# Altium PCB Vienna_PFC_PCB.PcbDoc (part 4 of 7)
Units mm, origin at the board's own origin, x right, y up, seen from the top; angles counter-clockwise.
Board outline 447.04 x 302.51 mm, 6 copper layers (Top Layer, Signal Layer 1, Signal Layer 2, Signal Layer 3, Signal Layer 4, Bottom Layer), stack 1.231 mm thick; 630 components, 255 nets, 1656 pads, 941 vias.
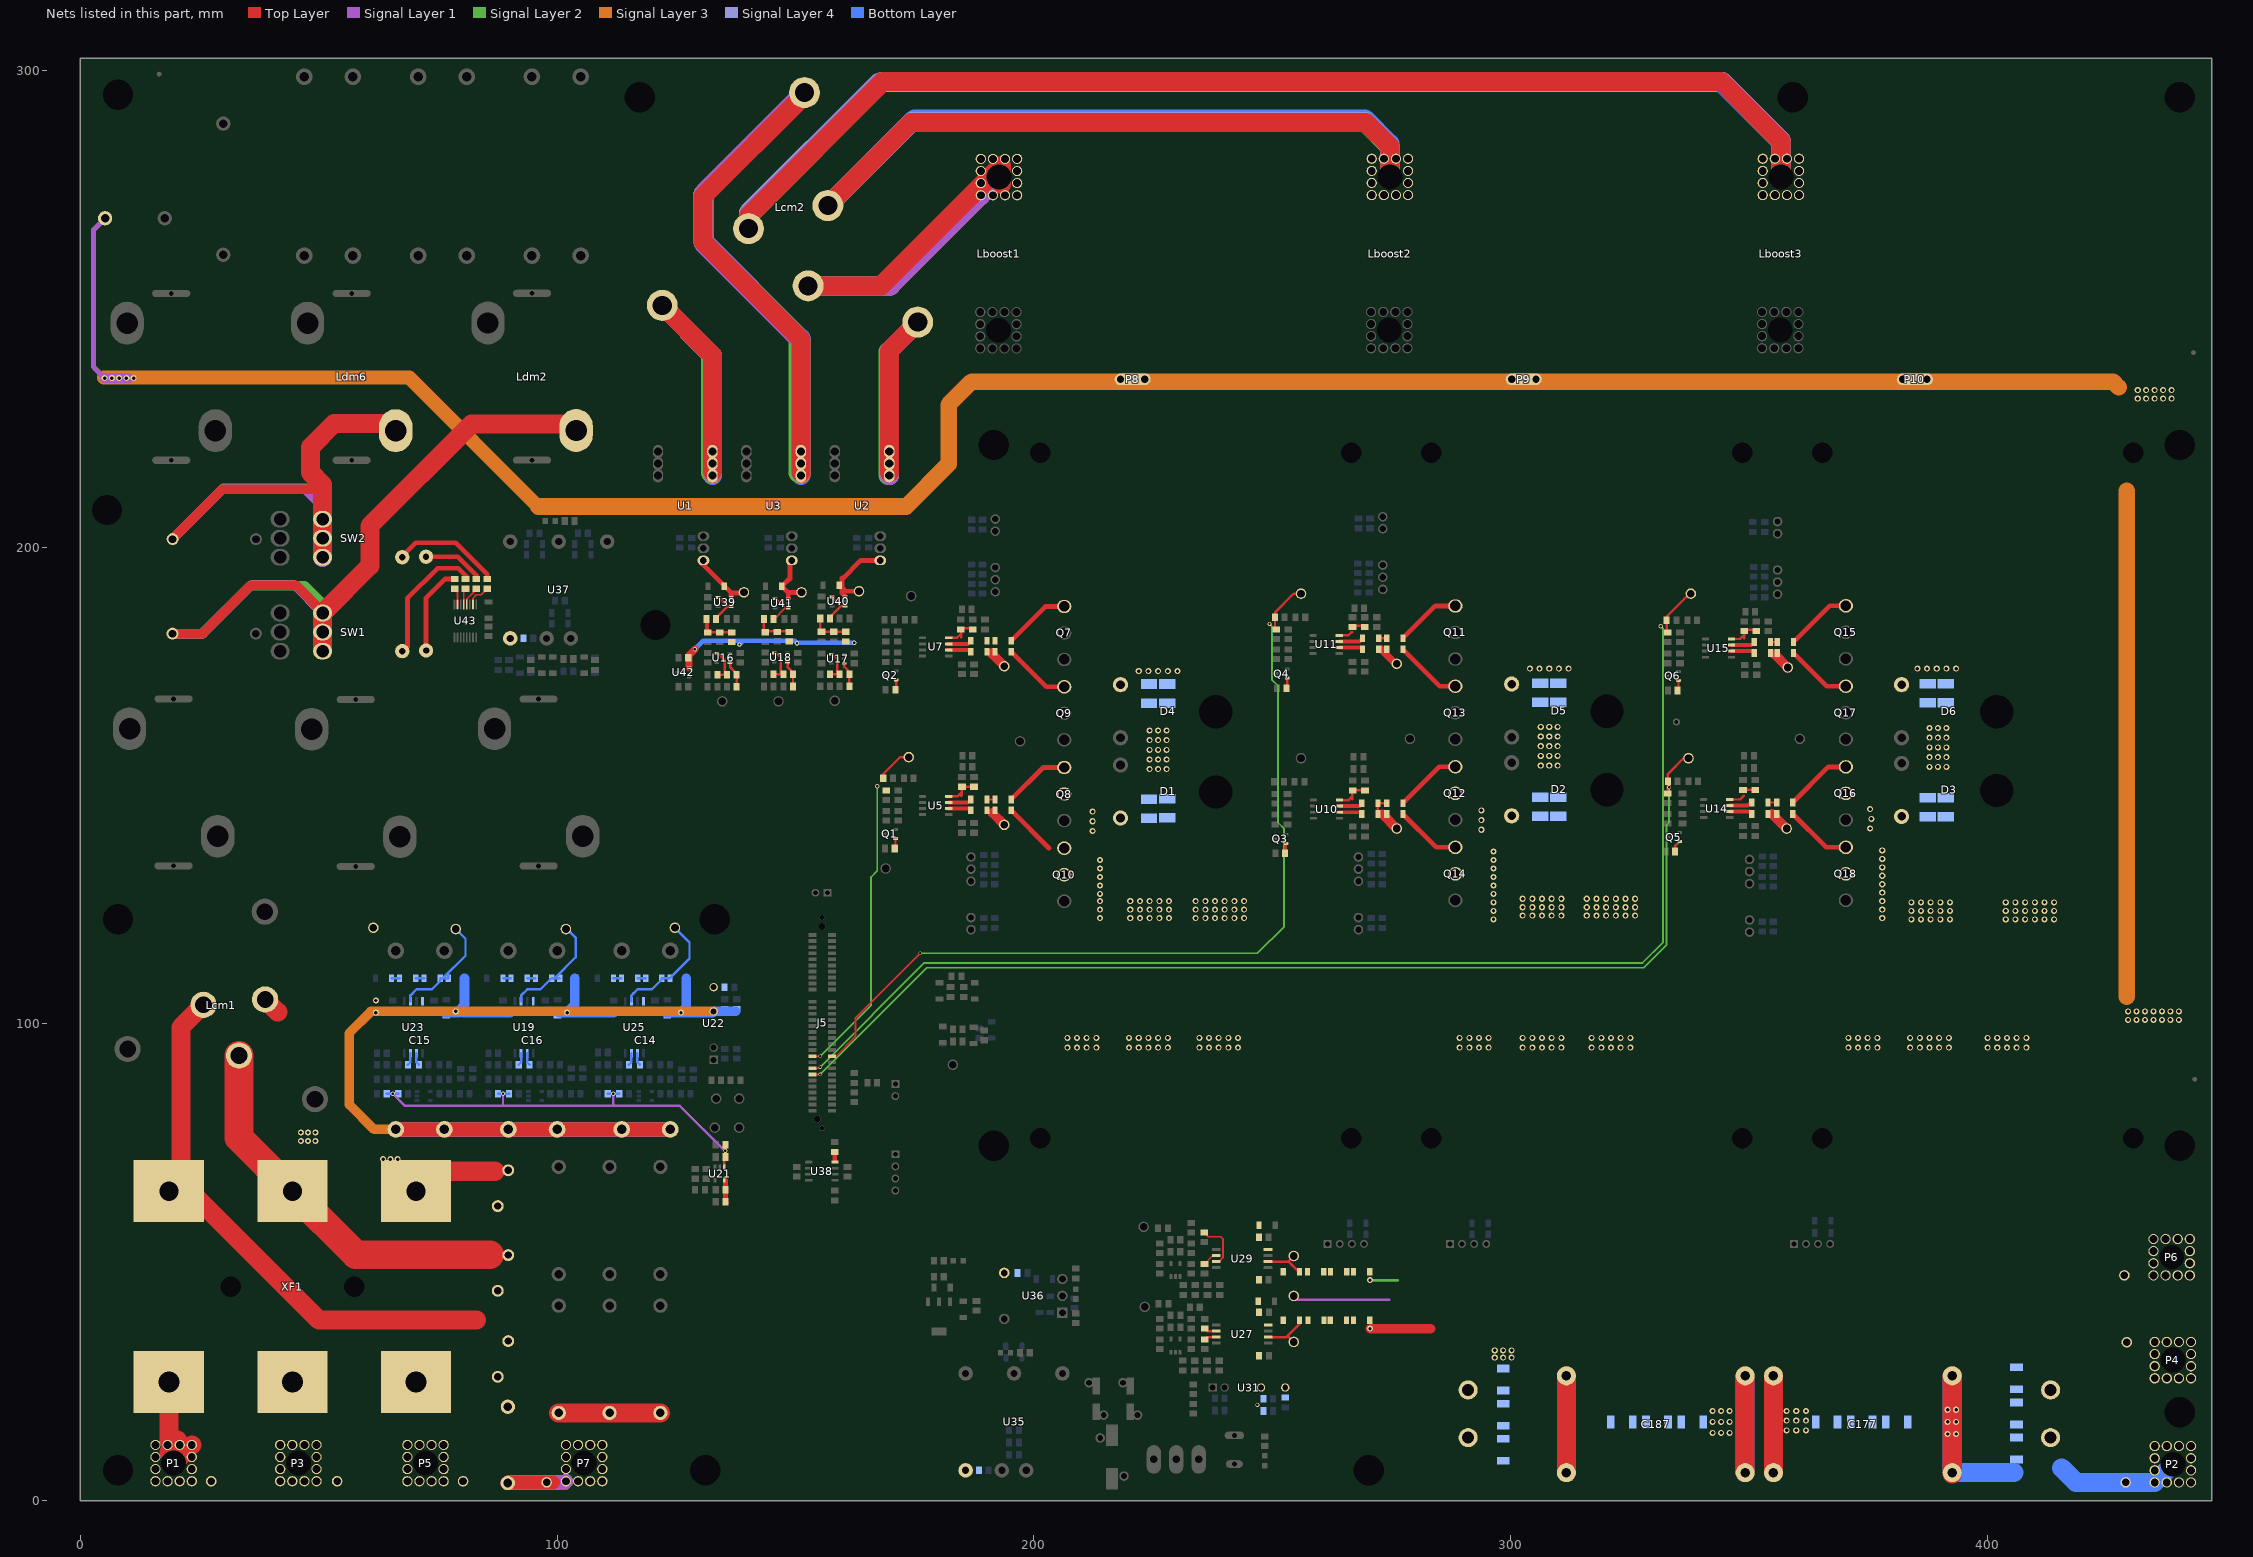
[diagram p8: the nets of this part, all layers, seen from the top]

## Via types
v1: diameter 1.27, hole 0.711, Top Layer to Bottom Layer, 487 vias
v2: diameter 0.889, hole 0.508, Top Layer to Bottom Layer, 425 vias
v3: diameter 0.762, hole 0.457, Top Layer to Bottom Layer, 28 vias
v4: diameter 0.889/0.889/0.889/0.889/0.889/0.889 (per signal layer), hole 0.508, Top Layer to Bottom Layer, 1 vias

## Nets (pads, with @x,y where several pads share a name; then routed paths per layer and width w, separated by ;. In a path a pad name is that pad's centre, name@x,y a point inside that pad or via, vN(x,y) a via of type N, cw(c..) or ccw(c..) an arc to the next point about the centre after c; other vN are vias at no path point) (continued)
NetJ5_41: J5.41 R7.1 R14.2 TP_G2.1 | length 70.9
  Top Layer w0.381: J5.41@153.565,93.218 v3(155.194,93.218)
  Top Layer w0.508: R14.2@168.402,151.511 168.402,152.4 171.958,155.956 TP_G2.1@173.736,155.956
  Signal Layer 2 w0.381: v3(155.194,93.218) 165.862,103.886 165.862,111.76 165.862,130.81 167.132,132.08 v2(167.132,149.86)
NetJ5_42: J5.42 R26.1 R33.2 TP_G3.1 | length 183.9
  Top Layer w0.381: J5.42@157.625,93.218 158.496,93.218 162.56,97.282 162.56,101.219 v3(176.149,114.808)
  Top Layer w0.508: R26.1@250.825,182.753 250.571,183.007 R33.2@250.571,185.293 250.571,186.309 254.508,190.246 TP_G3.1@256.032,190.246
  Signal Layer 2 w0.381: v3(176.149,114.808) 246.888,114.808 252.476,120.396 252.476,140.97 251.206,142.24 251.206,170.942 249.936,172.212 249.936,183.388 v2(249.428,183.896)
NetJ5_45: J5.45 R42.1 R49.2 TP_G5.1 | length 266.7
  Top Layer w0.381: J5.45@153.162,90.678 J5.45@153.565,90.678 154.94,90.678 v3(155.194,90.932)
  Top Layer w0.508: R42.1@332.994,182.118 332.74,182.372 R49.2@332.74,184.658 332.74,185.42 337.566,190.246 TP_G5.1@337.82,190.246
  Signal Layer 2 w0.381: v3(155.194,90.932) 177.038,112.776 327.66,112.776 331.978,117.094 331.978,182.88 v2(331.47,183.388)
NetJ5_47: J5.47 R40.1 R47.2 TP_G6.1 | length 233.4
  Top Layer w0.381: J5.47@153.565,89.408 v3(155.194,89.408)
  Top Layer w0.508: R40.1@332.994,148.336 332.994,152.4 336.296,155.702 TP_G6.1@337.312,155.702
  Signal Layer 2 w0.381: v3(155.194,89.408) 177.546,111.76 327.914,111.76 332.677,116.523 332.677,141.669 333.248,142.24 v2(333.248,149.606)
NetL5_1: L5.1 U22.7
NetL7_1: L7.1 U31.7
NetLboost1_1: Lboost1.1 Lcm2.2 | length 302.3
  Top Layer w4: Lcm2.2@152.658,254.814 167.945,254.813 193.192,280.06 Lboost1.1@193.192,276.098
  Signal Layer 1 w4: Lcm2.2@152.658,254.814 169.876,254.813 Lboost1.1@188.874,273.812 Lboost1.1@192.684,277.622
  Signal Layer 2 w4: Lcm2.2@152.658,254.814 169.469,254.813 192.278,277.622 Lboost1.1@192.684,277.622
  Signal Layer 3 w4: Lcm2.2@152.658,254.814 169.876,254.813 Lboost1.1@188.874,273.812 Lboost1.1@192.684,277.622
  Signal Layer 4 w4: Lcm2.2@152.658,254.814 169.876,254.813 Lboost1.1@188.874,273.812 Lboost1.1@192.684,277.622
  Bottom Layer w4: Lcm2.2@152.658,254.814 169.876,254.813 Lboost1.1@188.874,273.812 Lboost1.1@192.684,277.622
NetLboost2_1: Lboost2.1 Lcm2.4 | length 802.7
  Top Layer w4: Lcm2.4@156.775,271.638 174.189,289.052 269.672,289.052 274.676,284.048 Lboost2.1@274.676,277.647
  Signal Layer 1 w4: Lcm2.4@156.775,271.638 174.189,289.052 269.748,289.052 274.676,284.124 Lboost2.1@274.676,277.647
  Signal Layer 2 w4: Lcm2.4@156.775,271.638 174.189,289.052 269.494,289.052 274.676,283.87 Lboost2.1@274.676,277.647
  Signal Layer 3 w4: Lcm2.4@156.775,271.638 174.189,289.052 269.748,289.052 274.676,284.124 Lboost2.1@274.676,277.647
  Signal Layer 4 w4: Lcm2.4@156.775,271.638 156.83,271.638 174.498,289.306 269.494,289.306 274.676,284.124 Lboost2.1@274.676,277.647
  Bottom Layer w4: Lcm2.4@156.775,271.638 174.951,289.814 269.494,289.814 274.676,284.632 Lboost2.1@274.676,277.647
NetLboost3_1: Lboost3.1 Lcm2.6 | length 1462.5
  Top Layer w4: Lcm2.6@140.147,266.791 140.147,269.433 168.402,297.688 344.094,297.688 356.692,285.09 Lboost3.1@356.692,277.647
  Signal Layer 1 w4: Lcm2.6@140.147,266.791 140.147,269.687 168.148,297.688 344.424,297.688 356.692,285.42 Lboost3.1@356.692,277.647
  Signal Layer 2 w4: Lcm2.6@140.147,266.791 140.147,269.433 168.402,297.688 344.424,297.688 356.692,285.42 Lboost3.1@356.692,277.647
  Signal Layer 3 w4: Lcm2.6@140.147,266.791 140.147,269.687 168.148,297.688 344.17,297.688 356.692,285.166 Lboost3.1@356.692,277.647
  Signal Layer 4 w4: Lcm2.6@140.147,266.791 140.147,270.195 167.386,297.434 344.678,297.434 356.692,285.42 Lboost3.1@356.692,277.647
  Bottom Layer w4: Lcm2.6@140.147,266.791 140.147,269.941 167.64,297.434 344.17,297.434 356.692,284.912 Lboost3.1@356.692,277.647
NetLcm1_1: Lcm1.1 TVS3.2 XF1.2 | length 117.8
  Top Layer w4: Lcm1.1@25.808,103.994 21.082,99.268 21.082,67.432 XF1.2@18.542,64.892 22.992,64.892 50.038,37.846 83.058,37.846
NetLcm1_3: Lcm1.3 TVS1.2 XF1.6 | length 24.5
  Top Layer w4: Lcm1.3@38.749,105.126 41.402,102.473 ; XF1.6@67.95,64.892 XF1.6@70.358,64.892 70.988,64.892 75.184,69.088 86.978,69.088
  other v1: 63.5,71.628 65.024,71.628 66.548,71.628 46.228,75.438 47.752,75.438 49.276,75.438 46.228,77.216 47.752,77.216 49.276,77.216
NetLcm1_5: Lcm1.5 TVS2.2 XF1.4 | length 80
  Top Layer w6: Lcm1.5@33.259,93.353 33.259,76.083 XF1.4@44.45,64.892 57.8,51.542 85.852,51.542
NetLcm2_1: Lcm2.1 U1.4 U1.5 U1.6 | length 237.7
  Top Layer w4: Lcm2.1@122.057,250.703 132.588,240.172 U1.6@132.588,220.066 U1.5@132.588,217.526 U1.4@132.588,215.9
  Signal Layer 1 w4: Lcm2.1@122.057,250.703 132.588,240.172 U1.6@132.588,220.066 U1.5@132.588,217.526 U1.4@132.588,215.586
  Signal Layer 2 w4: Lcm2.1@122.057,250.703 132.222,240.538 132.222,215.586 U1.4@132.588,215.586
  Signal Layer 3 w4: Lcm2.1@122.057,250.703 132.588,240.172 U1.6@132.588,220.066 U1.5@132.588,217.526 U1.4@132.588,215.284
  Signal Layer 4 w4: Lcm2.1@122.057,250.703 132.588,240.172 U1.6@132.588,220.066 U1.5@132.588,217.526 U1.4@132.588,215.586
  Bottom Layer w4: Lcm2.1@122.057,250.703 132.588,240.172 U1.6@132.588,220.066 U1.5@132.588,217.526 U1.4@132.588,214.986
NetLcm2_3: Lcm2.3 U2.4 U2.5 U2.6 | length 208
  Top Layer w4: U2.4@169.672,215.646 U2.5@169.672,217.526 U2.6@169.672,220.066 169.672,241.228 Lcm2.3@175.636,247.191
  Signal Layer 1 w4: U2.4@169.672,214.986 U2.5@169.672,217.526 U2.6@169.672,220.066 169.672,241.228 Lcm2.3@175.636,247.191
  Signal Layer 2 w4: U2.6@169.4,220.059 U2.6@169.418,219.304 ; U2.4@169.418,214.986 U2.6@169.418,219.304 ; Lcm2.3@175.636,247.191 169.418,240.974 U2.6@169.418,219.304
  Signal Layer 3 w4: U2.4@169.672,215.284 U2.5@169.672,217.526 U2.6@169.672,220.066 169.672,241.228 Lcm2.3@175.636,247.191
  Signal Layer 4 w4: U2.4@169.672,214.986 U2.5@169.672,217.526 U2.6@169.672,220.066 169.672,241.228 Lcm2.3@175.636,247.191
  Bottom Layer w4: U2.4@169.672,214.986 U2.5@169.672,217.526 U2.6@169.672,220.066 169.672,241.228 Lcm2.3@175.636,247.191
NetLcm2_5: Lcm2.5 U3.4 U3.5 U3.6 | length 582.2
  Top Layer w4: U3.4@151.13,215.646 U3.5@151.13,217.526 U3.6@151.13,220.066 151.13,243.586 130.556,264.16 130.556,273.508 Lcm2.5@151.887,294.84
  Signal Layer 1 w4: U3.4@151.13,215.788 U3.5@151.13,217.526 U3.6@151.13,220.066 151.13,243.197 130.81,263.517 130.81,274.27 Lcm2.5@151.887,295.348
  Signal Layer 2 w4: U3.4@150.53,215.586 150.53,244.186 130.556,264.16 130.556,274.016 Lcm2.5@151.887,295.348
  Signal Layer 3 w4: U3.4@151.13,215.284 U3.5@151.13,217.526 U3.6@151.13,220.066 151.13,243.325 130.556,263.899 130.556,274.016 Lcm2.5@151.887,295.348
  Signal Layer 4 w4: U3.4@151.13,215.586 U3.5@151.13,217.526 U3.6@151.13,220.066 151.13,243.586 130.81,263.906 130.81,274.27 Lcm2.5@151.887,295.348
  Bottom Layer w4: U3.4@151.13,214.986 U3.5@151.13,217.526 U3.6@151.13,220.066 151.13,243.84 130.556,264.414 130.556,274.016 Lcm2.5@151.887,295.348
NetLdm2_1: Ldm2.1 Rsurge1.2 SW1.5 | length 214.2
  Top Layer w2: Rsurge1.2@19.317,181.864 25.654,181.864 35.814,192.024 45.212,192.024 50.81,186.426 SW1.5@50.81,186.182
  Top Layer w4: SW1.5@50.81,178.562 SW1.5@50.81,182.182 SW1.5@50.81,186.182 60.706,196.078 60.706,204.47 82.042,225.806 Ldm2.1@104.394,225.806
  Signal Layer 1 w2: Rsurge1.2@19.317,181.864 25.654,181.864 35.906,192.116 44.876,192.116 SW1.5@50.81,186.182 SW1.5@50.81,182.182 SW1.5@50.81,178.182
  Signal Layer 2 w2: Rsurge1.2@19.317,181.864 25.654,181.864 35.722,191.932 47.027,191.932 50.704,188.255 50.704,186.288 SW1.5@50.81,186.182 SW1.5@50.81,182.182 SW1.5@50.81,178.182
NetLdm6_1: Ldm6.1 Rsurge2.2 SW2.5 | length 176.1
  Top Layer w2: Rsurge2.2@19.558,201.93 29.718,212.09 50.546,212.09 50.8,211.836
  Top Layer w4: SW2.5@50.8,198.12 SW2.5@50.8,201.866 SW2.5@50.8,205.866 50.8,211.836 50.8,213.106 48.26,215.646 48.26,220.98 53.242,225.962 Ldm6.1@66.146,225.962
  Signal Layer 1 w2: Rsurge2.2@19.33,201.676 29.744,212.09 47.244,212.09 50.8,208.534 SW2.5@50.8,205.866
  Signal Layer 1 w4: SW2.5@50.8,197.866 SW2.5@50.8,201.866 SW2.5@50.8,205.866
  Signal Layer 2 w2: Rsurge2.2@19.33,201.676 29.998,212.344 48.006,212.344 50.8,209.55 SW2.5@50.8,205.866 SW2.5@50.8,201.866 SW2.5@50.8,197.866
NetP1_1: P1.1 TP_V1.1 XF1.1 | length 19.3
  Top Layer w4: 18.542,10.16 18.796,10.414 ; P1.1@18.542,12.7 XF1.1@18.542,24.892 ; P1.1@19.304,11.684 20.32,12.7 P1.1@20.32,12.446 ; P1.1@19.558,7.874 21.844,10.16 ; 22.098,10.414 P1.1@23.368,11.684
NetP3_1: P3.1 TP_V2.1 XF1.3
NetP5_1: P5.1 TP_V3.1 XF1.5
NetQ1_1: Q1.1 R19.2 | length 2.4
  Top Layer w0.381: R19.2@170.815,136.779 170.999,136.963 Q1.1@170.999,138.877
  Top Layer w0.508: R19.2@170.434,136.779 R19.2@170.618,136.963
NetQ2_1: Q2.1 R20.2 | length 2.2
  Top Layer w0.508: R20.2@170.942,170.053 171.126,170.237 Q2.1@171.126,172.151
NetQ3_1: Q3.1 R36.2 | length 2.2
  Top Layer w0.508: R36.2@252.681,135.763 252.865,135.947 Q3.1@252.865,137.861
NetQ4_1: Q4.1 R37.2 | length 2.2
  Top Layer w0.508: R37.2@252.984,170.434 253.168,170.618 Q4.1@253.168,172.532
NetQ5_1: Q5.1 R52.2 | length 2.8
  Top Layer w0.508: R52.2@334.702,136.328 R52.2@334.518,136.144 334.518,137.296 Q5.1@335.464,138.242
NetQ6_1: Q6.1 R53.2 | length 2.2
  Top Layer w0.508: R53.2@335.026,169.926 335.21,170.11 Q6.1@335.21,172.024
NetQ7_1: Q7.1 R138.2 | length 14.1
  Top Layer w1: R138.2@195.248,180.34 202.462,187.554 Q7.1@206.375,187.554
NetQ8_1: Q8.1 R139.1 | length 13.9
  Top Layer w1: R139.1@195.248,147.066 201.954,153.772 Q8.1@206.375,153.772
NetQ9_1: Q9.1 R140.2 | length 14.2
  Top Layer w1: R140.2@195.248,178.054 202.614,170.688 Q9.1@206.375,170.688
NetQ10_1: Q10.1 R141.1 | length 11.2
  Top Layer w1: R141.1@195.248,144.78 203.173,136.855
NetQ11_1: Q11.1 R142.2 | length 13.8
  Top Layer w1: R142.2@277.417,180.848 284.224,187.655 Q11.1@288.417,187.655
NetQ12_1: Q12.1 R143.1 | length 14.2
  Top Layer w1: R143.1@277.417,146.304 285.037,153.924 Q12.1@288.417,153.924
NetQ13_1: Q13.1 R144.2 | length 14.2
  Top Layer w1: R144.2@277.417,178.562 285.164,170.815 Q13.1@288.417,170.815
NetQ14_1: Q14.1 R145.1 | length 13.9
  Top Layer w1: R145.1@277.417,144.018 284.402,137.033 Q14.1@288.417,137.033
NetQ15_1: Q15.1 R150.2 | length 14.1
  Top Layer w1: R150.2@359.332,180.086 366.927,187.681 Q15.1@370.332,187.681
NetQ16_1: Q16.1 R151.1 | length 14.2
  Top Layer w1: R151.1@359.205,146.431 366.673,153.899 Q16.1@370.332,153.899
NetQ17_1: Q17.1 R154.2 | length 13.9
  Top Layer w1: R154.2@359.332,177.8 366.317,170.815 Q17.1@370.332,170.815
NetQ18_1: Q18.1 R155.1 | length 14
  Top Layer w1: R155.1@359.205,144.018 366.19,137.033 Q18.1@370.332,137.033
NetR5_1: R5.1 R8.2 U5.8 | length 7.7
  Top Layer w0.508: U5.8@182.137,147.701 183.976,147.701 184.912,148.637 ; 184.774,147.828 184.912,147.966 184.912,148.637 ; R5.1@187.452,149.733 R8.2@184.912,149.733 184.912,148.637
NetR6_1: R6.1 R10.2 U7.8 | length 7.5
  Top Layer w0.508: U7.8@182.137,180.975 183.885,180.975 184.774,181.864 ; 184.774,181.102 184.774,181.864 ; R6.1@187.198,183.007 184.658,183.007 184.774,182.891 184.774,181.864
NetR11_1: R11.1 U5.7 | length 4.9
  Top Layer w0.8: U5.7@182.137,146.431 186.133,146.431 R11.1@186.768,147.066
NetR11_2: R11.2 R13.2 R139.2 R141.2 TP_GS2.1 | length 6.9
  Top Layer w0.508: R13.2@190.168,144.78 191.262,144.78 191.262,144.272 ; R11.2@190.168,147.066 R139.2@191.848,147.066
  Top Layer w2: 191.262,144.272 TP_GS2.1@193.802,141.732
NetR12_1: R12.1 U7.7 | length 5.2
  Top Layer w0.8: U7.7@181.864,179.705 U7.7@182.137,179.705 186.133,179.705 R12.1@186.768,180.34
NetR12_2: R12.2 R15.2 R138.1 R140.1 TP_GS1.1 | length 3.8
  Top Layer w2: 191.262,177.8 191.262,177.546 TP_GS1.1@193.802,175.006
NetR13_1: R13.1 U5.6 | length 4.8
  Top Layer w0.8: U5.6@182.137,145.161 186.387,145.161 R13.1@186.768,144.78
NetR15_1: R15.1 U7.6 | length 5.2
  Top Layer w0.8: U7.6@181.864,178.435 U7.6@182.137,178.435 186.69,178.435 186.768,178.357 R15.1@186.768,178.054
NetR22_1: R22.1 R25.2 U10.8 | length 7.5
  Top Layer w0.508: U10.8@264.13,146.939 266.005,146.939 266.767,147.701 ; 266.767,147.066 266.767,147.701 ; R22.1@269.445,148.971 R25.2@266.905,148.971 266.767,148.833 266.767,147.701
NetR23_1: R23.1 R27.2 U11.8 | length 5.6
  Top Layer w0.508: U11.8@264.052,181.483 265.938,181.483 266.573,182.118 266.827,182.118 ; R27.2@266.827,183.515 R23.1@269.367,183.515
NetR28_1: R28.1 U10.7 | length 5.2
  Top Layer w0.508: R28.1@268.761,146.079 R28.1@268.761,146.304 R28.1@268.761,146.431
  Top Layer w0.8: U10.7@264.13,145.669 268.351,145.669 R28.1@268.761,146.079
NetR28_2: R28.2 R30.2 R143.2 R145.2 TP_GS4.1 | length 9.4
  Top Layer w0.508: 273.089,143.979 273.089,144.018 R30.2@272.161,144.018 R28.2@272.161,146.304 R143.2@274.017,146.304
  Top Layer w2: 273.089,143.979 TP_GS4.1@276.098,140.97
NetR29_1: R29.1 U11.7 | length 5.1
  Top Layer w0.8: U11.7@264.052,180.213 268.302,180.213 R29.1@268.937,180.848
NetR29_2: R29.2 R32.2 R142.1 R144.1 TP_GS3.1 | length 8.6
  Top Layer w0.508: R32.2@272.337,178.562 272.796,178.562 R144.1@273.558,178.562 ; R29.2@272.337,180.848 R142.1@274.017,180.848 ; 273.05,179.07 R144.1@273.558,178.562 ; R144.1@274.017,178.562 R144.1@273.558,178.562
  Top Layer w1.524: R32.2@272.796,178.562 275.844,175.514 TP_GS3.1@276.098,175.514
NetR30_1: R30.1 U10.6 | length 4.8
  Top Layer w0.8: U10.6@264.13,144.399 268.38,144.399 R30.1@268.761,144.018
NetR32_1: R32.1 U11.6 | length 5
  Top Layer w0.8: U11.6@264.052,178.943 268.556,178.943 R32.1@268.937,178.562
NetR38_1: R38.1 R41.2 U14.8 | length 6
  Top Layer w0.508: U14.8@345.967,147.066 348.107,147.066 348.869,147.828 ; R41.2@348.604,148.96 R41.2@348.742,149.098 R38.1@351.282,149.098
NetR39_1: R39.1 R43.2 U15.8 | length 7.2
  Top Layer w0.508: U15.8@346.337,180.721 348.107,180.721 348.742,181.356 348.974,181.356 ; 348.974,180.848 348.974,181.356 ; R39.1@351.536,182.626 348.996,182.626 348.974,182.604 348.974,181.356
NetR44_1: R44.1 U14.7 | length 4.9
  Top Layer w0.508: R44.1@350.393,146.431 R44.1@350.598,146.431
  Top Layer w0.8: U14.7@345.967,145.796 349.758,145.796 R44.1@350.393,146.431
NetR44_2: R44.2 R46.2 R151.2 R155.2 TP_GS6.1 | length 7
  Top Layer w0.508: R46.2@353.998,144.145 354.838,144.145 ; R44.2@353.998,146.431 R151.2@355.805,146.431
  Top Layer w2: 354.838,144.018 TP_GS6.1@357.886,140.97
NetR45_1: R45.1 U15.7 | length 5
  Top Layer w0.8: U15.7@346.337,179.451 350.471,179.451 R45.1@351.106,180.086
NetR45_2: R45.2 R48.2 R150.1 R154.1 TP_GS5.1 | length 6.5
  Top Layer w0.508: R48.2@354.506,177.8 355.346,177.8 355.346,177.546 ; R45.2@354.506,180.086 R150.1@355.932,180.086
  Top Layer w2: 355.346,177.546 TP_GS5.1@358.14,174.752
NetR46_1: R46.1 U14.6 | length 7.4
  Top Layer w0.508: 348.604,144.653 350.09,144.653 350.598,144.145 R46.1@350.598,144.526 ; R46.1@350.09,144.526 R46.1@350.598,144.018
  Top Layer w0.8: U14.6@345.967,144.526 R46.1@350.09,144.526
NetR48_1: R48.1 U15.6 | length 4.9
  Top Layer w0.8: U15.6@346.337,178.181 350.725,178.181 R48.1@351.106,177.8
NetR54_1: R54.1 R57.2 R61.2 R67.1 | length 10.4
  Top Layer w0.508: R61.2@131.318,184.658 131.318,182.626 R57.2@131.572,182.372 ; R61.2@131.318,185.166 R61.2@131.318,184.912 131.572,184.658 R61.2@131.572,184.912 ; R61.2@131.572,184.404 R57.2@131.572,182.372 ; R54.1@136.398,182.118 R67.1@134.112,182.118 R57.2@131.572,182.118 R57.2@131.572,182.372
NetR56_1: R56.1 R58.2 U16.1 | length 5.5
  Top Layer w0.508: U16.1@136.503,175.834 136.271,175.602 136.271,174.879 R58.2@137.414,173.736 ; R56.1@137.668,170.688 R58.2@137.668,173.228 ; R58.2@137.668,173.482 R58.2@137.668,173.736
NetR58_1: R58.1 R59.2 U16.4 | length 7.5
  Top Layer w0.508: R59.2@133.604,173.228 R58.1@135.128,173.228 ; U16.4@133.753,177.734 135.128,176.359 R58.1@135.128,173.228 ; R58.1@135.382,173.482 R58.1@135.636,173.228 R58.1@135.128,173.228
NetR60_1: R60.1 R63.2 R172.2 R173.1 | length 8
  Top Layer w0.508: R172.2@155.194,185.039 155.194,182.499 R63.2@155.448,182.245 R173.1@157.988,182.245 R60.1@160.528,182.245
NetR61_1: R61.1 U39.1 U39.4 | length 7.2
  Top Layer w0.508: R61.1@133.35,184.912 133.35,185.141 135.727,187.518 135.824,187.518 ; U39.4@133.753,189.418 133.924,189.418 135.824,187.518 ; U39.1@136.503,187.518 135.824,187.518
NetR62_1: R62.1 R64.2 U17.1 | length 5.3
  Top Layer w0.508: U17.1@160.23,175.641 160.23,174.923 161.29,173.863 R64.2@161.29,173.355 R62.1@161.29,170.815
NetR64_1: R64.1 R65.2 U17.4 | length 6.8
  Top Layer w0.508: R65.2@157.226,173.355 R64.1@159.004,173.355 ; U17.4@157.734,177.541 158.75,176.525 158.75,173.863 R64.1@159.258,173.355 R64.1@159.512,173.355
NetR66_1: R66.1 R69.2 R175.2 R176.1 | length 8
  Top Layer w0.508: R175.2@143.383,184.912 143.383,182.401 R69.2@143.637,182.147 ; R69.2@143.637,182.323 R66.1@148.717,182.323
NetR68_1: R68.1 R70.2 U18.1 | length 5.7
  Top Layer w0.508: U18.1@148.568,175.912 148.336,175.68 148.336,174.879 149.479,173.736 R70.2@149.479,173.306 R68.1@149.479,170.766
NetR70_1: R70.1 R71.2 U18.4 | length 7.3
  Top Layer w0.508: R71.2@145.415,173.306 R70.1@146.939,173.306 ; U18.4@145.564,177.812 145.911,177.812 146.939,176.784 R70.1@146.939,173.306 ; R70.1@147.447,173.306 R70.1@146.939,173.306
NetR72_1: R72.1 R73.2 | length 1.7
  Bottom Layer w0.508: R72.1@88.646,109.601 R73.2@90.326,109.601
NetR73_1: R73.1 R75.2 | length 1.7
  Bottom Layer w0.508: R73.1@93.726,109.601 R75.2@95.455,109.601
NetR75_1: R75.1 R78.2 TP_VLI1.1 U19.2 | length 23.6
  Bottom Layer w0.508: U19.2@92.456,104.764 92.456,105.96 93.76,107.264 96.518,107.264 R75.1@98.601,109.347 ; R75.1@98.855,109.601 99.519,109.601 ; R78.2@100.535,109.601 99.519,109.601 ; TP_VLI1.1@101.854,120.142 103.886,118.11 103.886,113.968 99.519,109.601
NetR76_1: R76.1 U19.6 | length 2.6
  Bottom Layer w0.508: U19.6@93.726,93.864 93.726,91.948 R76.1@94.234,91.44
NetR80_1: R80.1 U19.7 | length 2.6
  Bottom Layer w0.508: R80.1@91.948,91.44 92.456,91.948 U19.7@92.456,93.864
NetR84_1: R84.1 R85.2 | length 1.7
  Bottom Layer w0.508: R84.1@65.278,109.601 R85.2@66.958,109.601
NetR85_1: R85.1 R87.2 | length 1.7
  Bottom Layer w0.508: R85.1@70.358,109.601 R87.2@72.087,109.601
NetR87_1: R87.1 R90.2 TP_VLI2.1 U23.2 | length 24.4
  Bottom Layer w0.508: U23.2@69.215,104.764 69.215,105.96 70.519,107.264 73.736,107.264 R87.1@75.487,109.015 ; R87.1@75.487,109.269 R87.1@75.487,109.601 76.073,109.601 ; R90.2@77.167,110.187 R90.2@77.167,109.601 76.073,109.601 ; TP_VLI2.1@78.74,119.888 80.772,117.856 80.772,114.3 76.073,109.601
NetR88_1: R88.1 U23.6 | length 2.6
  Bottom Layer w0.508: U23.6@70.485,93.864 70.485,91.948 R88.1@70.993,91.44
NetR92_1: R92.1 U23.7 | length 2.6
  Bottom Layer w0.508: R92.1@68.707,91.44 69.215,91.948 U23.7@69.215,93.864
NetR96_1: R96.1 R97.2 | length 1.7
  Bottom Layer w0.508: R96.1@111.809,109.601 R97.2@113.489,109.601
NetR97_1: R97.1 R99.2 | length 1.7
  Bottom Layer w0.508: R97.1@116.889,109.601 R99.2@118.569,109.601
NetR99_1: R99.1 R102.2 TP_VLI3.1 U25.2 | length 24.2
  Bottom Layer w0.508: U25.2@115.57,104.764 115.57,105.918 116.002,106.35 116.002,106.392 116.874,107.264 119.886,107.264 R99.1@121.969,109.347 ; R99.1@121.969,109.601 R102.2@123.649,109.601 127.762,113.714 127.762,117.094 TP_VLI3.1@124.714,120.142
NetR100_1: R100.1 U25.6 | length 2.6
  Bottom Layer w0.508: U25.6@116.84,93.864 116.84,91.948 R100.1@117.348,91.44
NetR104_1: R104.1 U25.7 | length 2.6
  Bottom Layer w0.508: R104.1@115.062,91.44 115.57,91.948 U25.7@115.57,93.864
NetR108_1: R108.1 R109.2
NetR109_1: R109.1 R111.2
NetR111_1: R111.1 R114.2 TP_VPM.1 U27.2 | length 10.6
  Top Layer w0.508: U27.2@249.138,34.292 251.208,34.292 ; 250.952,34.29 252.984,34.29 253.238,34.544 ; TP_VPM.1@254.508,33.274 253.238,34.544 ; R114.2@255.723,37.846 255.723,37.029 253.238,34.544
NetR112_1: R112.1 U27.6 | length 2.6
  Top Layer w0.508: R112.1@235.814,36.07 236.322,35.562 U27.6@238.238,35.562
NetR116_1: R116.1 U27.7 | length 2.6
  Top Layer w0.508: R116.1@235.814,33.784 236.322,34.292 U27.7@238.238,34.292
NetR120_1: R120.1 R121.2
NetR121_1: R121.1 R123.2
NetR123_1: R123.1 R126.2 TP_VNM.1 U29.2 | length 8.9
  Top Layer w0.508: U29.2@249.112,50.14 253.39,50.14 ; TP_VNM.1@254,50.8 253.365,50.165 253.39,50.14 ; 254.127,49.403 253.39,50.14 ; 254.254,49.276 R126.2@255.778,47.752 ; R126.2@255.524,48.514 R126.2@256.032,48.514
NetR124_1: R124.1 U29.7 | length 10.3
  Top Layer w0.381: R124.1@235.712,56.261 236.613,55.36 239.219,55.36 239.649,54.93 239.649,50.927 238.862,50.14 U29.7@238.212,50.14
NetR128_1: R128.1 U29.6 | length 3.2
  Top Layer w0.381: R128.1@235.788,49.632 237.566,51.41 U29.6@238.212,51.41
NetR132_1: R132.1 R134.2
NetR133_1: R133.1 R135.2
NetR134_1: R134.1 R136.2
NetR135_1: R135.1 R137.2
NetR146_1: R146.1 R148.2
NetR147_1: R147.1 R149.2
NetR148_1: R148.1 R152.2
NetR149_1: R149.1 R153.2
NetR167_2: R167.2 U36.4
NetR168_1: R168.1 U35.3
NetR170_1: R170.1 U37.3
NetR171_2: R171.2 TP_IIn1.1 U1.7 U39.3 | length 15
  Top Layer w0.508: 136.503,190.395 136.608,190.5 TP_IIn1.1@139.192,190.5
  Top Layer w1.016: U1.7@130.315,196.583 R171.2@135.128,191.77 ; R171.2@135.128,191.516 R171.2@135.128,191.77 ; 136.503,189.843 136.503,190.395 ; TP_IIn1.1@139.192,190.5 139.087,190.395 136.503,190.395 ; R171.2@135.128,191.77 136.503,190.395
NetR172_1: R172.1 U40.1 U40.4 | length 7.1
  Top Layer w0.508: R172.1@157.226,185.039 157.226,185.342 159.529,187.645 ; U40.4@157.629,189.545 159.529,187.645 ; U40.1@160.379,187.645 159.529,187.645
NetR174_2: R174.2 TP_IIn2.1 U2.7 U40.3 | length 17.6
  Top Layer w1.016: 159.766,193.548 159.766,193.294 ; U40.3@160.379,189.708 159.766,190.321 159.766,191.516 ; TP_IIn2.1@163.322,190.754 160.528,190.754 159.766,191.516 ; U2.7@167.767,197.206 163.678,197.206 159.766,193.294 ; 159.766,191.516 159.766,193.294
NetR175_1: R175.1 U41.1 U41.4 | length 6.4
  Top Layer w0.381: R175.1@145.415,184.912 145.537,184.912 147.889,187.264 145.989,189.164 U41.4@145.713,189.164
NetR177_2: R177.2 TP_IIn3.1 U3.7 U41.3 | length 12.2
  Top Layer w1.016: U41.3@148.463,189.327 148.463,190.422 ; 148.844,193.245 148.844,193.499 ; U3.7@148.844,197.206 148.844,193.499 ; TP_IIn3.1@151.257,190.5 148.541,190.5 148.463,190.422 ; 148.463,190.422 R177.2@147.115,191.77 148.844,193.499
NetR178_1: R178.1 U38.8 | length 1.8
  Top Layer w1.016: 158.242,71.374 R178.1@158.242,73.152
NetR180_1: R180.1 U43.15 | length 4.1
  Top Layer w0.33: R180.1@78.74,191.262 R180.1@79.106,190.896 ; 79.101,189.209 79.101,188.976 79.106,188.971 U43.15@79.106,187.96
  Top Layer w0.508: R180.1@78.486,191.262 79.101,190.647 79.101,189.209
NetR180_2: R180.2 SW1.1 | length 18.6
  Top Layer w1.016: SW1.1@72.51,178.31 72.51,189.35 76.454,193.294 R180.2@78.486,193.294
NetR181_1: R181.1 U43.13 | length 3.5
  Top Layer w0.33: U43.13@80.406,187.96 80.406,190.896 R181.1@80.772,191.262
NetR181_2: R181.2 SW1.2 | length 26.7
  Top Layer w1.016: SW1.2@68.072,178.562 68.58,179.07 68.58,189.23 74.93,195.58 79.248,195.58 R181.2@81.026,193.802
NetR182_1: R182.1 U43.12 | length 3.5
  Top Layer w0.33: U43.12@81.056,187.96 81.056,189.097 R182.1@82.713,190.754
NetR182_2: R182.2 SW2.1 | length 13
  Top Layer w1.016: SW2.1@72.5,197.994 79.12,197.994 83.058,194.056 R182.2@83.058,193.294
NetR183_1: R183.1 U43.10 | length 5.1
  Top Layer w0.33: U43.10@82.356,187.96 82.356,189.29 83.058,189.992 84.074,189.992 R183.1@85.344,191.262
NetR183_2: R183.2 SW2.2 | length 22.3
  Top Layer w1.016: SW2.2@67.818,198.374 70.358,200.914 78.74,200.914 85.344,194.31 R183.2@85.344,193.294
NetTVS1_1: TVS1.1 TVS2.1 TVS3.1 XF2.1
PE: C8.1 C9.1 C10.1 P7.1 TP_PE1.1 XF2.2 | length 90.9
  Top Layer w3: XF2.2@89.662,3.684 89.788,3.81 TP_PE1.1@97.79,3.81 99.06,3.81
  Top Layer w4: C8.1@100.33,18.394 C9.1@110.998,18.394 C10.1@121.666,18.394
  Signal Layer 1 w3: XF2.2@89.662,3.684 89.788,3.81 TP_PE1.1@97.79,3.81 101.6,3.81 P7.1@101.854,4.064
  Signal Layer 2 w3: XF2.2@89.662,3.684 89.788,3.81 TP_PE1.1@97.79,3.81 100.33,3.81
  Signal Layer 3 w3: XF2.2@89.662,3.684 101.474,3.684 P7.1@101.854,4.064
  Signal Layer 4 w3: XF2.2@89.662,3.684 89.788,3.81 TP_PE1.1@97.79,3.81 101.6,3.81 P7.1@101.854,4.064
  Bottom Layer w3: XF2.2@89.662,3.684 101.474,3.684 P7.1@101.854,4.064
REF_1V65: C127.1 C128.1 C129.1 C142.1 C152.1 R83.1 R95.1 R107.1 U21.1 | length 91.3
  Top Layer w0.508: U21.1@135.052,69.952 C127.1@135.052,71.824 ; C127.1@135.306,72.078 v2(135.306,73.406) C128.1@135.306,74.618
  Signal Layer 1 w0.508: v2(65.532,85.344) 68.072,82.804 88.646,82.804 ; v2(88.646,85.344) 88.646,82.804 ; v2(111.76,85.344) 111.76,82.804 ; v2@135.217,73.317 125.73,82.804 111.76,82.804 ; 88.646,82.804 111.76,82.804
  Bottom Layer w0.508: C142.1@64.262,85.344 v2(65.532,85.344) R95.1@66.675,85.344 ; C129.1@87.63,85.344 v2(88.646,85.344) R83.1@89.916,85.344 ; C152.1@110.617,85.344 v2(111.76,85.344) R107.1@113.03,85.344
REF_3V3: C121.1 C220.1 U21.5 | length 4.8
  Top Layer w1.016: U21.5@135.306,67.234 C121.1@135.306,65.22 C220.1@135.306,62.68 C220.1@135.501,62.484
REF_3V3_2: C253.1 R54.2 R60.2 R66.2 U42.2 | length 39.9
  Top Layer w1.5: U42.2@127.692,174.686 127.692,177.349 v2(128.905,178.562)
  Bottom Layer w1: v2(128.905,178.562) 130.683,180.34 139.016,180.34 ; v2(138.254,179.578) 139.016,180.34 ; v2(162.306,179.959) 150.446,179.959 v2(150.319,179.832) 149.811,180.34 139.016,180.34
V_BUS_M: C154.1 C161.2 C163.1 C170.2 C172.2 C173.2 C174.2 C175.2 C176.2 C177.1 C178.1 C179.1 C180.2 C181.2 C182.1 C183.1 C184.2 C185.2 C186.1 C187.2 C188.1 C189.1 P4.1 P8.1 P9.1 P10.1 Q8.2 Q10.2 Q12.2 Q14.2 Q16.2 Q18.2 R4.2 R114.1 R118.2 R126.1 R130.2 R136.1 R137.1 R146.2 R147.2 TP_BUSM.1 TP_N1.1 U27.4 U29.4 U31.5 | length 861.3
  Top Layer w4: C187.2@349.182,5.852 C187.2@349.182,26.162 ; C177.1@355.138,5.852 C177.1@355.138,26.152
  Signal Layer 1 w0.508: TP_BUSM.1@255.27,42.164 274.574,42.164
  Signal Layer 1 w1: v1(5.08,235.458) 2.794,237.744 2.794,266.6 R4.2@5.18,268.986
  Signal Layer 1 w2: v1(5.08,235.458) v1(6.604,235.458) v1(8.128,235.458) v1(9.652,235.458) v1@10.16,235.458
  Signal Layer 2 w1: R4.2@5.18,268.986 2.794,266.6 2.794,237.744 v1(5.08,235.458) v1(6.604,235.458) v1(8.128,235.458) v1(9.652,235.458) v1(11.176,235.458)
  Signal Layer 3 w0.508: TP_BUSM.1@254.254,43.18 TP_BUSM.1@254.508,42.926 TP_BUSM.1@255.27,42.164
  Signal Layer 3 w1: v1@4.953,235.585 2.794,237.744 2.794,266.6 R4.2@5.18,268.986
  Signal Layer 3 w3: v1@4.953,235.585 68.961,235.585 96.012,208.534
  Signal Layer 3 w3.5: 96.012,208.534 173.228,208.534 182.118,217.424 182.118,229.87 186.944,234.696 300.228,234.696 382.27,234.696 426.374,234.696 427.563,233.507 ; 429.26,105.664 429.26,211.836
  Signal Layer 4 w1: R4.2@5.18,268.986 2.794,266.6 2.794,237.744 v1(5.08,235.458) v1(6.604,235.458) v1(8.128,235.458) v1(9.652,235.458) v1(11.176,235.458) v1@11.43,235.458
  Bottom Layer w1: R4.2@5.18,268.986 2.794,266.6 2.794,237.744 v1(5.08,235.458) v1(6.604,235.458) v1(8.128,235.458) v1(9.652,235.458) v1(11.176,235.458)
  Bottom Layer w4: C187.2@349.204,5.852 C187.2@349.204,26.152 ; C177.1@355.138,5.852 C177.1@355.138,26.152
  other v1: 342.392,14.224 344.17,14.224 345.948,14.224 357.886,14.732 359.918,14.732 361.95,14.732 342.392,16.51 344.17,16.51 345.948,16.51 357.886,16.764 359.918,16.764 361.95,16.764 342.392,18.796 344.17,18.796 345.948,18.796 357.886,18.796 359.918,18.796 361.95,18.796 296.672,29.972 298.45,29.972 300.228,29.972 296.672,31.496 298.45,31.496 300.228,31.496 207.01,94.996 209.042,94.996 211.074,94.996 213.106,94.996 289.306,94.996 291.338,94.996 293.37,94.996 295.402,94.996 370.84,94.996 372.872,94.996 374.904,94.996 376.936,94.996 207.01,97.073 209.042,97.073 211.074,97.073 213.106,97.073 289.306,97.073 291.338,97.073 293.37,97.073 295.402,97.073 370.84,97.073 372.872,97.073 374.904,97.073 376.936,97.073 429.514,100.838 431.292,100.838 433.07,100.838 434.848,100.838 436.626,100.838 438.404,100.838 440.182,100.838 429.514,102.616 431.292,102.616 433.07,102.616 434.848,102.616 436.626,102.616 438.404,102.616 440.182,102.616 296.418,121.92 213.868,122.174 377.952,122.174 296.418,123.698 213.868,123.952 377.952,123.952 296.418,125.476 213.868,125.73 377.952,125.73 213.868,127.254 296.418,127.254 377.952,127.508 213.868,129.032 296.418,129.032 377.952,129.286 213.868,130.81 296.418,130.81 377.952,131.064 213.868,132.588 296.418,132.588 377.952,132.842 213.868,134.366 296.418,134.366 377.952,134.62 296.418,136.144 377.952,136.398 212.344,140.462 293.878,140.716 375.412,140.97 212.344,142.494 293.878,142.748 375.666,143.002 212.344,144.526 293.878,144.78 375.412,145.034 224.282,153.416 226.06,153.416 227.838,153.416 387.858,153.924 389.636,153.924 391.414,153.924 306.324,154.178 308.102,154.178 309.88,154.178 224.282,155.448 226.06,155.448 227.838,155.448 387.858,155.956 389.636,155.956 391.414,155.956 306.324,156.21 308.102,156.21 309.88,156.21 224.282,157.48 226.06,157.48 227.838,157.48 387.858,157.988 389.636,157.988 391.414,157.988 306.324,158.242 308.102,158.242 309.88,158.242 224.282,159.512 226.06,159.512 227.838,159.512 387.858,160.02 389.636,160.02 391.414,160.02 306.324,160.274 308.102,160.274 309.88,160.274 224.282,161.544 226.06,161.544 227.838,161.544 387.858,162.052 389.636,162.052 391.414,162.052 306.324,162.306 308.102,162.306 309.88,162.306 431.546,231.14 433.324,231.14 435.102,231.14 436.88,231.14 438.658,231.14 431.546,232.918 433.324,232.918 435.102,232.918 436.88,232.918 438.658,232.918
  other v2: 246.888,20.066
V_N_MEAS: C14.1 C15.1 C16.1 C116.1 C126.2 C131.1 C136.2 C137.2 C141.2 C144.1 C151.2 R78.1 R82.2 R90.1 R94.2 R102.1 R106.2 TP_VLM.1 U19.4 U22.5 U23.4 U25.4 | length 513.4
  Top Layer w3: C15.1@66.167,77.851 C15.1@76.367,77.851 ; C15.1@76.494,77.851 C16.1@89.789,77.851 C16.1@99.989,77.851 C14.1@113.538,77.851 C14.1@123.738,77.851
  Signal Layer 1 w3: C15.1@66.167,77.851 C15.1@76.367,77.851 C16.1@89.789,77.851 C16.1@99.989,77.851 C14.1@113.538,77.851 C14.1@123.738,77.851
  Signal Layer 2 w3: C15.1@66.167,77.851 C15.1@76.367,77.851 C16.1@89.789,77.851 C16.1@99.989,77.851 C14.1@113.538,77.851 C14.1@123.738,77.851
  Signal Layer 3 w2: C15.1@66.167,77.851 61.595,77.851 56.388,83.058 56.388,98.044 60.96,102.616 v1(78.74,102.616) U22.5@132.842,102.616
  Signal Layer 3 w3: C15.1@66.167,77.851 C15.1@76.367,77.851 C16.1@89.789,77.851 C16.1@99.989,77.851 C14.1@113.538,77.851 C14.1@123.738,77.851
  Signal Layer 4 w3: C15.1@66.167,77.851 C15.1@76.367,77.851 C16.1@89.789,77.851 C16.1@99.989,77.851 C14.1@113.538,77.851 C14.1@123.738,77.851
  Bottom Layer w2: 76.454,102.362 v1@78.994,102.362 ; v1(78.74,102.616) v1@79.248,102.616 ; 80.264,102.362 90.17,102.362 ; R90.1@80.567,109.601 80.567,103.935 v1@79.248,102.616 ; 100.33,102.362 v1(102.108,102.362) 103.681,103.935 R78.1@103.681,109.601 ; v1@102.362,102.362 C144.1@111.887,102.362 ; 122.936,102.362 v1(125.984,102.362) ; R102.1@127.049,109.601 127.049,103.427 v1(125.984,102.362) ; U22.5@132.588,102.362 v1(125.984,102.362) ; U22.5@132.842,102.616 C137.2@137.414,102.616 ; v1@78.994,102.362 79.502,102.362 v1@79.248,102.616 ; v1@78.994,102.362 v1@79.248,102.616
  Bottom Layer w3: C15.1@66.167,77.851 C15.1@76.367,77.851 C16.1@89.789,77.851 C16.1@99.989,77.851 C14.1@113.538,77.851 C14.1@123.738,77.851
  other v1: 61.976,102.362 61.976,104.902
VBUSN: C178.2 C179.2 C182.2 C183.2 C186.2 C187.1 C188.2 C189.2 D4.2 D5.2 D6.2 P6.1 R120.2 R152.1 R153.1 TP_VL8.1 | length 52.3
  Top Layer w4: C187.1@311.704,5.852 C187.1@311.704,26.152
  Signal Layer 2 w0.508: v1(270.51,46.228) 276.352,46.228
  Signal Layer 3 w0.508: v1(270.51,46.228) 276.352,46.228
  Bottom Layer w4: C187.1@311.704,5.852 C187.1@311.704,26.152
  other v1: 234.696,94.996 236.728,94.996 238.76,94.996 240.792,94.996 242.824,94.996 316.992,94.996 319.024,94.996 321.056,94.996 323.088,94.996 325.12,94.996 400.05,94.996 402.082,94.996 404.114,94.996 406.146,94.996 408.178,94.996 234.696,97.073 236.728,97.073 238.76,97.073 240.792,97.073 242.824,97.073 316.992,97.073 319.024,97.073 321.056,97.073 323.088,97.073 325.12,97.073 400.05,97.073 402.082,97.073 404.114,97.073 406.146,97.073 408.178,97.073 403.86,121.92 405.892,121.92 407.924,121.92 409.956,121.92 411.988,121.92 414.02,121.92 233.934,122.174 235.966,122.174 237.998,122.174 240.03,122.174 242.062,122.174 244.094,122.174 315.976,122.682 318.008,122.682 320.04,122.682 322.072,122.682 324.104,122.682 326.136,122.682 403.86,123.698 405.892,123.698 407.924,123.698 409.956,123.698 411.988,123.698 414.02,123.698 233.934,123.952 235.966,123.952 237.998,123.952 240.03,123.952 242.062,123.952 244.094,123.952 315.976,124.46 318.008,124.46 320.04,124.46 322.072,124.46 324.104,124.46 326.136,124.46 403.86,125.476 405.892,125.476 407.924,125.476 409.956,125.476 411.988,125.476 414.02,125.476 233.934,125.73 235.966,125.73 237.998,125.73 240.03,125.73 242.062,125.73 244.094,125.73 315.976,126.238 318.008,126.238 320.04,126.238 322.072,126.238 324.104,126.238 326.136,126.238 221.996,173.99 224.028,173.99 226.06,173.99 228.092,173.99 230.124,173.99 304.038,174.498 306.07,174.498 308.102,174.498 310.134,174.498 312.166,174.498 385.318,174.498 387.35,174.498 389.382,174.498 391.414,174.498 393.446,174.498
VBUSP: C174.1 C175.1 C176.1 C177.2 C180.1 C181.1 C184.1 C185.1 D1.1 D2.1 D3.1 P2.1 R108.2 R132.2 R133.2 TP_VL7.1 | length 92.7
  Top Layer w2: v1(270.51,36.068) 283.21,36.068
  Top Layer w4: C177.2@392.638,5.61 C177.2@392.638,5.852 C177.2@392.638,26.152
  Bottom Layer w4: C177.2@392.638,26.152 C177.2@392.638,5.852 405.628,5.852 ; 415.544,6.858 418.592,3.81 TP_VL7.1@429.006,3.81 P2.1@435.102,3.81 P2.1@438.912,7.62
  other v1: 391.668,13.97 393.446,13.97 391.668,16.51 393.446,16.51 391.668,19.05 393.446,19.05 219.964,94.996 221.996,94.996 224.028,94.996 226.06,94.996 228.092,94.996 302.514,94.996 304.546,94.996 306.578,94.996 308.61,94.996 310.642,94.996 383.794,94.996 385.826,94.996 387.858,94.996 389.89,94.996 391.922,94.996 219.964,97.073 221.996,97.073 224.028,97.073 226.06,97.073 228.092,97.073 302.514,97.073 304.546,97.073 306.578,97.073 308.61,97.073 310.642,97.073 383.794,97.073 385.826,97.073 387.858,97.073 389.89,97.073 391.922,97.073 384.048,121.92 386.08,121.92 388.112,121.92 390.144,121.92 392.176,121.92 220.218,122.174 222.25,122.174 224.282,122.174 226.314,122.174 228.346,122.174 302.514,122.682 304.546,122.682 306.578,122.682 308.61,122.682 310.642,122.682 384.048,123.698 386.08,123.698 388.112,123.698 390.144,123.698 392.176,123.698 220.218,123.952 222.25,123.952 224.282,123.952 226.314,123.952 228.346,123.952 302.514,124.46 304.546,124.46 306.578,124.46 308.61,124.46 310.642,124.46 384.048,125.476 386.08,125.476 388.112,125.476 390.144,125.476 392.176,125.476 220.218,125.73 222.25,125.73 224.282,125.73 226.314,125.73 228.346,125.73 302.514,126.238 304.546,126.238 306.578,126.238 308.61,126.238 310.642,126.238
pads on no net: D1.0 D2.0 D3.0 D4.0 D5.0 D6.0 FID1.1 FID2.1 FID3.1 FID4.1 FID5.1 FID6.1 Hole1.0 Hole2.0 Hole3.0 Hole4.0 Hole5.0 Hole6.0 Hole7.0 Hole8.0 Hole9.0 Hole10.0 Hole11.0 Hole12.0 J5.0 J5.4 J5.6 J5.7 J5.8 J5.10 J5.18 J5.19 J5.23 J5.26 J5.28 J5.29 J5.30 J5.32 J5.34 J5.36 J5.38 J5.39 J5.43 J5.44 J5.46 J5.48 J5.49 J5.50 J5.51 J5.52 J5.53 J5.55 J5.56 J7.3 J7.4 J8.3 J8.4 J9.3 J9.4 Ldm1.0 Ldm2.0 Ldm3.0 Ldm4.0 Ldm5.0 Ldm6.0 S1.1 U35.5 U36.5 U43.1 U43.2 W1.0 W2.0 W3.0 W4.0 W5.0 W6.0 W7.0 W8.0 W9.0 W10.0 W11.0 W12.0 W13.0 W14.0 W15.0 W16.0 XF1.0

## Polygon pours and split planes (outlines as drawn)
DGND on Top Layer "NONET_L-01_P-001" (solid, remove dead copper, pour order 568): 361.95,207.772 330.2,207.772 330.2,184.404 330.2,132.842 330.2,102.87 361.95,102.87 361.95,123.444 349.25,123.444 345.694,123.444 341.63,127.508 340.36,128.778 340.36,188.468 340.36,197.612 344.17,201.422 361.95,201.422
DGND on Top Layer "NONET_L-01_P-001" (solid, remove dead copper, pour order 538): 361.95,102.87 201.93,102.87 201.93,90.17 184.15,90.17 184.15,117.348 302.006,117.348 361.84,117.348 361.95,117.238
GND on Top Layer "DGND" (solid, remove dead copper, pour order 1496): 55 vertices, not listed, extent 88.392,2.54 240.538,203.708
DGND2 on Top Layer "NONET_L-01_P-001" (solid, remove dead copper, pour order 1480): 89.281,171.45 82.423,171.45 82.042,171.45 78.232,175.26 77.47,176.022 77.47,191.008 78.232,191.77 85.852,191.77 85.979,191.77 86.233,191.516 86.614,191.135 86.614,185.674 86.614,177.292 89.281,174.625
DGND on Top Layer "NONET_L-01_P-001" (solid, remove dead copper, pour order 548): 198.12,208.534 181.356,208.534 165.354,192.532 165.354,132.08 181.356,116.078 202.438,116.078 202.438,124.206 185.42,124.206 181.864,124.206 177.8,128.27 176.53,129.54 176.53,189.23 176.53,198.374 180.34,202.184 198.12,202.184
V_BUS_M on Top Layer "NONET_L-01_P-001" (solid, remove dead copper, pour order 1066): 34 vertices, not listed, extent 368.554,102.87 393.192,168.91
VBUSN on Top Layer "NONET_L-01_P-001" (solid, remove dead copper, pour order 950): 314.96,120.65 326.898,120.65 326.898,139.192 326.898,175.26 326.949,175.311 326.912,175.274 298.891,175.274 298.891,171.517 298.958,171.45 303.784,171.45 312.166,171.45 313.436,170.18 314.96,168.656
VBUSP on Top Layer "NONET_L-01_P-001" (solid, remove dead copper, pour order 942): 312.166,120.65 299.72,120.65 299.72,142.748 301.244,144.272 312.166,144.272
V_BUS_M on Top Layer "NONET_L-01_P-001" (solid, remove dead copper, pour order 1042): 34 vertices, not listed, extent 287.02,120.65 311.658,168.91
VBUSN on Top Layer "NONET_L-01_P-001" (solid, remove dead copper, pour order 920): 232.918,120.65 245.11,120.65 245.11,175.514 244.87,175.274 216.849,175.274 216.849,171.517 216.916,171.45 221.742,171.45 230.124,171.45 231.394,170.18 232.918,168.656
VBUSP on Top Layer "NONET_L-01_P-001" (solid, remove dead copper, pour order 900): 230.124,120.65 217.678,120.65 217.678,142.748 219.202,144.272 230.124,144.272
V_BUS_M on Top Layer "NONET_L-01_P-001" (solid, remove dead copper, pour order 1024): 35 vertices, not listed, extent 204.978,120.65 229.616,168.402
GND on Top Layer "NONET_L-01_P-001" (solid, remove dead copper, pour order 839): 61.468,96.52 61.366,96.418 61.366,84.328 61.366,84.176 62.992,82.55 84.328,82.55 139.954,82.55 139.954,96.52
VBUSP on Top Layer "NONET_L-01_P-001" (solid, remove dead copper, pour order 494): 301.015,66.802 301.015,46.99 276.885,46.99 274.345,46.99 274.345,2.032 424.205,2.032 424.205,54.61 424.205,66.802
GND_IN on Top Layer "NONET_L-01_P-001" (solid, remove dead copper, pour order 1460): 189.23,14.986 183.896,9.652 180.086,5.842 180.086,3.302 181.356,2.032 190.246,2.032 254,2.032 255.27,3.302 255.27,14.478 254.762,14.986
DGND on Top Layer "NONET_L-01_P-001" (solid, remove dead copper, pour order 562): 280.162,208.788 248.412,208.788 248.412,185.42 248.412,133.858 248.412,102.87 280.162,102.87 280.162,124.46 267.462,124.46 263.906,124.46 259.842,128.524 258.572,129.794 258.572,189.484 258.572,198.628 262.382,202.438 280.162,202.438
NetC10_2 on Top Layer "NONET_L-01_P-001" (solid, remove dead copper, pour order 1204): 26 vertices, not listed, extent 36.068,120.904 110.236,145.796
NetC20_1 on Top Layer "NONET_L-01_P-001" (solid, remove dead copper, pour order 1432): 12.7,276.86 10.16,274.32 10.16,264.16 12.7,261.62 13.97,260.35 30.48,260.35 33.02,262.89 33.782,263.652 33.782,273.812 30.734,276.86
NetC17_1 on Top Layer "NONET_L-01_P-001" (solid, remove dead copper, pour order 1420): 110.744,297.18 107.95,299.974 107.696,300.228 104.902,300.228 20.828,300.228 15.748,295.402 10.922,290.322 10.16,289.56 4.572,289.56 2.54,287.528 2.54,282.956 4.572,280.924 40.132,280.924 107.442,280.924 110.513,283.995
NetLboost3_1 on Top Layer "NONET_L-01_P-001" (solid, remove dead copper, pour order 1408): 38 vertices, not listed, extent 137.16,263.398 362.458,300.228
NetLboost2_1 on Top Layer "NONET_L-01_P-001" (solid, remove dead copper, pour order 1396): 20 vertices, not listed, extent 148.844,265.176 280.416,293.37
NetLboost1_1 on Top Layer "NONET_L-01_P-001" (solid, remove dead copper, pour order 1384): 150.114,256.286 151.384,255.016 151.384,252.476 172.466,252.476 189.23,269.24 195.58,269.24 198.374,272.034 198.374,282.448 197.612,283.21 178.054,283.21 152.4,257.556
NetLcm2_3 on Top Layer "NONET_L-01_P-001" (solid, remove dead copper, pour order 1372): 161.29,247.65 161.29,231.14 163.83,228.6 163.83,214.122 167.64,210.312 173.99,210.312 177.492,210.312 180.34,212.658 180.34,236.982 180.34,248.92 177.8,251.46 164.754,251.46
NetLcm2_5 on Top Layer "NONET_L-01_P-001" (solid, remove dead copper, pour order 1360): 32 vertices, not listed, extent 118.618,213.36 159.004,299.72
NetLcm2_1 on Top Layer "NONET_L-01_P-001" (solid, remove dead copper, pour order 1338): 123.444,254.254 117.856,248.666 120.65,245.872 128.27,238.252 128.27,228.092 128.27,215.392 129.794,213.868 130.302,213.36 133.35,213.36 134.112,213.36 135.128,214.376 135.636,214.884 135.636,235.966 135.636,242.062 131.318,246.38
NetC19_2 on Top Layer "NONET_L-01_P-001" (solid, remove dead copper, pour order 1336): 25 vertices, not listed, extent 77.47,212.852 125.222,264.16
NetC17_2 on Top Layer "NONET_L-01_P-001" (solid, remove dead copper, pour order 1324): 34 vertices, not listed, extent 44.196,213.614 143.51,278.13
NetC18_2 on Top Layer "NONET_L-01_P-001" (solid, remove dead copper, pour order 1312): 51 vertices, not listed, extent 5.08,205.232 162.814,278.13
NetC16_2 on Top Layer "NONET_L-01_P-001" (solid, remove dead copper, pour order 1268): 27 vertices, not listed, extent 34.544,156.21 99.06,189.23
NetC14_2 on Top Layer "NONET_L-01_P-001" (solid, remove dead copper, pour order 1206): 30 vertices, not listed, extent 10.414,154.686 52.07,209.296
NetLdm2_1 on Top Layer "NONET_L-01_P-001" (solid, remove dead copper, pour order 1212): 27 vertices, not listed, extent 46.99,175.26 107.442,231.648
NetLdm6_1 on Top Layer "NONET_L-01_P-001" (solid, remove dead copper, pour order 1210): 47.752,196.596 48.26,196.088 53.848,196.088 54.356,196.596 54.61,196.85 54.61,207.518 63.5,216.408 70.866,223.774 70.866,228.346 68.58,230.632 53.594,230.632 43.434,230.632 40.894,228.092 40.894,212.852 47.752,205.994
NetC15_2 on Top Layer "NONET_L-01_P-001" (solid, remove dead copper, pour order 1208): 31 vertices, not listed, extent 2.54,154.432 38.862,230.124
NetC8_2 on Top Layer "NONET_L-01_P-001" (solid, remove dead copper, pour order 1200): 32 vertices, not listed, extent 26.292,81.156 70.104,146.434
NetC9_2 on Top Layer "NONET_L-01_P-001" (solid, remove dead copper, pour order 1198): 17 vertices, not listed, extent 2.54,90.17 32.258,146.812
NetD3_2 on Top Layer "NONET_L-01_P-001" (solid, pour order 1162): 362.287,237.744 366.859,233.172 362.287,233.172
NetD2_2 on Top Layer "NONET_L-01_P-001" (solid, pour order 1160): 280.299,237.607 284.871,233.035 280.299,233.035
NetD1_2 on Top Layer "NONET_L-01_P-001" (solid, pour order 1146): 197.949,237.744 202.521,233.172 197.949,233.172
NetD3_2 on Top Layer "NONET_L-01_P-001" (solid, pour order 1134): 366.903,207.137 361.061,212.979 366.903,212.979
NetD2_2 on Top Layer "NONET_L-01_P-001" (solid, pour order 1124): 331.089,212.725 325.247,206.883 325.247,212.725
NetD2_2 on Top Layer "NONET_L-01_P-001" (solid, pour order 1114): 286.004,207.645 280.162,213.487 286.004,213.487
NetD1_2 on Top Layer "NONET_L-01_P-001" (solid, pour order 1104): 249.682,214.63 243.84,208.788 243.84,214.63
NetD1_2 on Top Layer "NONET_L-01_P-001" (solid, pour order 1086): 204.006,207.01 198.164,212.852 204.006,212.852
NetTVS1_1 on Top Layer "NONET_L-01_P-001" (solid, remove dead copper, pour order 1070): 96.139,63.246 88.138,63.246 87.884,63.246 86.868,62.23 86.868,61.214 87.63,60.452 87.884,60.198 87.884,27.432 86.868,26.416 86.868,25.4 86.868,25.146 86.868,18.034 93.726,18.034 93.726,21.603 96.139,23.889
V_N_MEAS on Top Layer "NONET_L-01_P-001" (solid, remove dead copper, pour order 849): 135.636,101.6 61.468,101.6 61.214,101.854 61.214,110.49 135.636,110.49
NetQ18_1 on Top Layer "NONET_L-01_P-001" (solid, remove dead copper, pour order 827): 358.648,144.78 358.648,134.874 371.348,134.874 371.348,137.16 363.728,144.78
